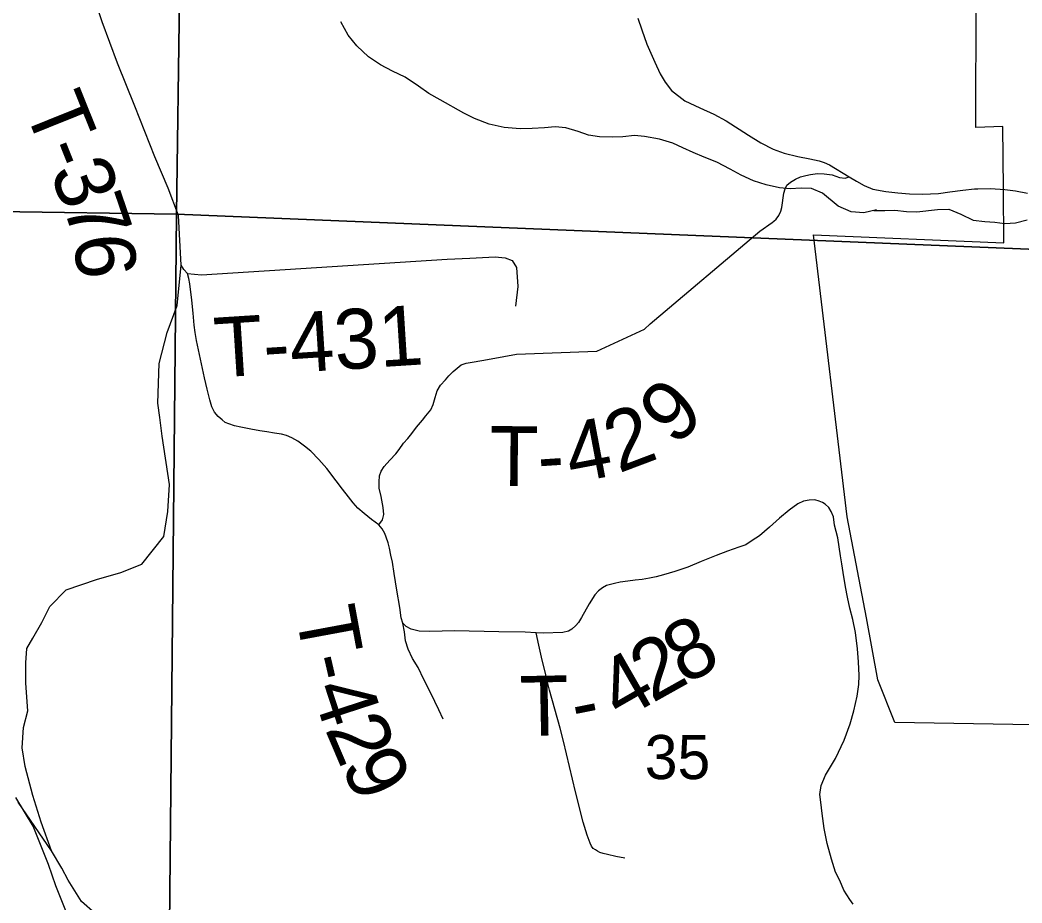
# Model space of a CAD drawing. Extents: x 2.1 to 8.9, y 14.1 to 20.9.
# Drawn here: x 6.298 to 7.249, y 17.436 to 18.274 of the extents above; entities that cross this region are included whole.
import ezdxf

# ---------------------------------------------------------------- set-up
doc = ezdxf.new("R2010")
doc.units = 0
for name, color, linetype in [('GM_X_City_Street', 7, 'Continuous'), ('GM_X_County_Road_Text', 7, 'Continuous'), ('GM_X_Interchange_Ramps', 7, 'Continuous'), ('GM_X_Minor_River_Text', 7, 'Continuous'), ('GM_X_State_Shield', 7, 'Continuous'), ('GM_X_Township_Road', 7, 'Continuous'), ('TX_P_Misc', 7, 'Continuous')]:
    doc.layers.add(name, color=color, linetype=linetype)

msp = doc.modelspace()

# ---------------------------------------------------------------- linework, layer by layer
at = {"layer": 'GM_X_City_Street'}
for p, q in [((6.3759, 18.27213), (6.36046, 18.31774)), ((6.39039, 18.23269), (6.3759, 18.27213)), ((6.40679, 18.19182), (6.39039, 18.23269)), ((6.4258, 18.14383), (6.40679, 18.19182)), ((6.43839, 18.11413), (6.4258, 18.14383)), ((7.0258, 18.11686), (7.02928, 18.11968)), ((7.02928, 18.11968), (7.03402, 18.12265)), ((7.03402, 18.12265), (7.03889, 18.12481)), ((7.03889, 18.12481), (7.04369, 18.12614)), ((7.04369, 18.12614), (7.04808, 18.12715)), ((7.04808, 18.12715), (7.05496, 18.12796)), ((7.05496, 18.12796), (7.06115, 18.12777)), ((7.06115, 18.12777), (7.06886, 18.12659)), ((7.06886, 18.12659), (7.07574, 18.12416)), ((7.07574, 18.12416), (7.08117, 18.12353)), ((7.08117, 18.12353), (7.08485, 18.12478)), ((6.44813, 18.08823), (6.43839, 18.11413)), ((7.02292, 18.10949), (7.02415, 18.11339)), ((7.02415, 18.11339), (7.0258, 18.11686)), ((7.02118, 18.09573), (7.02292, 18.10949)), ((7.01806, 18.08829), (7.02001, 18.09218)), ((7.02001, 18.09218), (7.02118, 18.09573)), ((6.45066, 18.04112), (6.44813, 18.08823)), ((7.0002, 18.07328), (7.0118, 18.08148)), ((7.0118, 18.08148), (7.01336, 18.08278)), ((7.01336, 18.08278), (7.0157, 18.08473)), ((7.0157, 18.08473), (7.01806, 18.08829)), ((6.89603, 17.98525), (7.0002, 18.07328)), ((6.46999, 18.03192), (6.70343, 18.04657)), ((6.70343, 18.04657), (6.72492, 18.04774)), ((6.72492, 18.04774), (6.74902, 18.04876)), ((6.74902, 18.04876), (6.75825, 18.04799)), ((6.75825, 18.04799), (6.76517, 18.04543)), ((6.76517, 18.04543), (6.76927, 18.03863)), ((6.44698, 18.00266), (6.45066, 18.04112)), ((6.45337, 18.03703), (6.45066, 18.04112)), ((6.45668, 18.03305), (6.45337, 18.03703)), ((6.76927, 18.03863), (6.77043, 18.02069)), ((6.45817, 18.02841), (6.45668, 18.03305)), ((6.45668, 18.03305), (6.46999, 18.03192)), ((6.45916, 18.02328), (6.45817, 18.02841)), ((6.46098, 18.00771), (6.45916, 18.02328)), ((6.77043, 18.02069), (6.76813, 18.00214)), ((6.46231, 17.99529), (6.46098, 18.00771)), ((6.43743, 17.97713), (6.44698, 18.00266)), ((6.46314, 17.98402), (6.46231, 17.99529)), ((6.43003, 17.94771), (6.43743, 17.97713)), ((6.46413, 17.97723), (6.46314, 17.98402)), ((6.46546, 17.96945), (6.46413, 17.97723)), ((6.8454, 17.95934), (6.89067, 17.98034)), ((6.89067, 17.98034), (6.89603, 17.98525)), ((6.47306, 17.93407), (6.46546, 17.96945)), ((6.76901, 17.95636), (6.8454, 17.95934)), ((6.71659, 17.94639), (6.72136, 17.94803)), ((6.72136, 17.94803), (6.72716, 17.94907)), ((6.72716, 17.94907), (6.73625, 17.95056)), ((6.73625, 17.95056), (6.74518, 17.95214)), ((6.74518, 17.95214), (6.76901, 17.95636)), ((6.42867, 17.90991), (6.43003, 17.94771)), ((6.70483, 17.93596), (6.709, 17.94013)), ((6.709, 17.94013), (6.71287, 17.94326)), ((6.71287, 17.94326), (6.71659, 17.94639)), ((6.47556, 17.92324), (6.47306, 17.93407)), ((6.69702, 17.92721), (6.70165, 17.93218)), ((6.70165, 17.93218), (6.70483, 17.93596)), ((6.47788, 17.9133), (6.47556, 17.92324)), ((6.69188, 17.91529), (6.69387, 17.92158)), ((6.69387, 17.92158), (6.69702, 17.92721)), ((6.43061, 17.89646), (6.42867, 17.90991)), ((6.47987, 17.90667), (6.47788, 17.9133)), ((6.69006, 17.90883), (6.69188, 17.91529)), ((6.48252, 17.90154), (6.47987, 17.90667)), ((6.486, 17.8974), (6.48252, 17.90154)), ((6.6831, 17.89789), (6.68791, 17.90369)), ((6.68791, 17.90369), (6.69006, 17.90883)), ((6.43276, 17.87873), (6.43061, 17.89646)), ((6.48964, 17.89408), (6.486, 17.8974)), ((6.49246, 17.89176), (6.48964, 17.89408)), ((6.4961, 17.89044), (6.49246, 17.89176)), ((6.67432, 17.88713), (6.67996, 17.89375)), ((6.67996, 17.89375), (6.6831, 17.89789)), ((6.50157, 17.88845), (6.4961, 17.89044)), ((6.50753, 17.88713), (6.50157, 17.88845)), ((6.5168, 17.88531), (6.50753, 17.88713)), ((6.52542, 17.88382), (6.5168, 17.88531)), ((6.53204, 17.88282), (6.52542, 17.88382)), ((6.5395, 17.88166), (6.53204, 17.88282)), ((6.54596, 17.8805), (6.5395, 17.88166)), ((6.66588, 17.87653), (6.66985, 17.88133)), ((6.66985, 17.88133), (6.67432, 17.88713)), ((6.43977, 17.83294), (6.43276, 17.87873)), ((6.55092, 17.87918), (6.54596, 17.8805)), ((6.55573, 17.87719), (6.55092, 17.87918)), ((6.56169, 17.87404), (6.55573, 17.87719)), ((6.56799, 17.86907), (6.56169, 17.87404)), ((6.65776, 17.86609), (6.66174, 17.87189)), ((6.66174, 17.87189), (6.66588, 17.87653)), ((6.57395, 17.86444), (6.56799, 17.86907)), ((6.58157, 17.85665), (6.57395, 17.86444)), ((6.65445, 17.86195), (6.65776, 17.86609)), ((6.58919, 17.84804), (6.58157, 17.85665)), ((6.64352, 17.85003), (6.64882, 17.85582)), ((6.64882, 17.85582), (6.65445, 17.86195)), ((6.5978, 17.83628), (6.58919, 17.84804)), ((6.63904, 17.84091), (6.64053, 17.84539)), ((6.64053, 17.84539), (6.64352, 17.85003)), ((6.60393, 17.82833), (6.5978, 17.83628)), ((6.63871, 17.83545), (6.63904, 17.84091)), ((6.63888, 17.82932), (6.63871, 17.83545)), ((6.43821, 17.80722), (6.43977, 17.83294)), ((6.60956, 17.8212), (6.60393, 17.82833)), ((6.64053, 17.82137), (6.63888, 17.82932)), ((6.6142, 17.81524), (6.60956, 17.8212)), ((6.6185, 17.81044), (6.6142, 17.81524)), ((6.64269, 17.81093), (6.64053, 17.82137)), ((7.04154, 17.81706), (7.03624, 17.81458)), ((7.04684, 17.81806), (7.04154, 17.81706)), ((7.05247, 17.81839), (7.04684, 17.81806)), ((7.05661, 17.81706), (7.05247, 17.81839)), ((7.05959, 17.81574), (7.05661, 17.81706)), ((7.06224, 17.81408), (7.05959, 17.81574)), ((6.43432, 17.78346), (6.43821, 17.80722)), ((6.62447, 17.80514), (6.6185, 17.81044)), ((6.64328, 17.80434), (6.64269, 17.81093)), ((7.02796, 17.80845), (7.01885, 17.80083)), ((7.03624, 17.81458), (7.02796, 17.80845)), ((7.06556, 17.8111), (7.06224, 17.81408)), ((7.06787, 17.80729), (7.06556, 17.8111)), ((7.07003, 17.80199), (7.06787, 17.80729)), ((6.63159, 17.79951), (6.62447, 17.80514)), ((6.63855, 17.79437), (6.63159, 17.79951)), ((6.63855, 17.79437), (6.64202, 17.79917)), ((6.64202, 17.79917), (6.64328, 17.80434)), ((7.01885, 17.80083), (7.00924, 17.79222)), ((7.07102, 17.79421), (7.07003, 17.80199)), ((6.64153, 17.79056), (6.63855, 17.79437)), ((6.64401, 17.78642), (6.64153, 17.79056)), ((6.6455, 17.78294), (6.64401, 17.78642)), ((7.00924, 17.79222), (6.9998, 17.7841)), ((7.07417, 17.78228), (7.07102, 17.79421)), ((6.41342, 17.75728), (6.43432, 17.78346)), ((6.64716, 17.77748), (6.6455, 17.78294)), ((6.64848, 17.77234), (6.64716, 17.77748)), ((6.99301, 17.77963), (6.98688, 17.77565)), ((6.9998, 17.7841), (6.99301, 17.77963)), ((7.07682, 17.76522), (7.07417, 17.78228)), ((6.64981, 17.76572), (6.64848, 17.77234)), ((6.96932, 17.76953), (6.95872, 17.76555)), ((6.98025, 17.77317), (6.96932, 17.76953)), ((6.98688, 17.77565), (6.98025, 17.77317)), ((6.6513, 17.75892), (6.64981, 17.76572)), ((6.65312, 17.74832), (6.6513, 17.75892)), ((6.94431, 17.75959), (6.93172, 17.75445)), ((6.95872, 17.76555), (6.94431, 17.75959)), ((7.07798, 17.75743), (7.07682, 17.76522)), ((6.37056, 17.74246), (6.39351, 17.74933)), ((6.39351, 17.74933), (6.41342, 17.75728)), ((6.65561, 17.73242), (6.65312, 17.74832)), ((6.91946, 17.75015), (6.9087, 17.747)), ((6.93172, 17.75445), (6.91946, 17.75015)), ((7.07914, 17.74915), (7.07798, 17.75743)), ((7.08146, 17.73574), (7.07914, 17.74915)), ((6.34159, 17.73283), (6.37056, 17.74246)), ((6.86232, 17.73888), (6.8547, 17.7369)), ((6.86762, 17.74004), (6.86232, 17.73888)), ((6.87474, 17.74104), (6.86762, 17.74004)), ((6.88187, 17.74186), (6.87474, 17.74104)), ((6.88849, 17.74269), (6.88187, 17.74186)), ((6.89545, 17.74385), (6.88849, 17.74269)), ((6.90158, 17.74501), (6.89545, 17.74385)), ((6.9087, 17.747), (6.90158, 17.74501)), ((6.32599, 17.71689), (6.34159, 17.73283)), ((6.65826, 17.71603), (6.65561, 17.73242)), ((6.84692, 17.73176), (6.8436, 17.72812)), ((6.85089, 17.73474), (6.84692, 17.73176)), ((6.8547, 17.7369), (6.85089, 17.73474)), ((7.08344, 17.7258), (7.08146, 17.73574)), ((6.8436, 17.72812), (6.83806, 17.71959)), ((7.0856, 17.71553), (7.08344, 17.7258)), ((6.31844, 17.70179), (6.32599, 17.71689)), ((6.65958, 17.70609), (6.65826, 17.71603)), ((6.83806, 17.71959), (6.831, 17.7066)), ((7.08858, 17.7046), (7.0856, 17.71553)), ((6.30991, 17.68702), (6.31844, 17.70179)), ((6.66115, 17.70101), (6.65958, 17.70609)), ((6.66455, 17.69814), (6.66115, 17.70101)), ((6.66267, 17.69286), (6.66115, 17.70101)), ((6.82803, 17.70178), (6.82538, 17.6988)), ((6.831, 17.7066), (6.82803, 17.70178)), ((7.0909, 17.69217), (7.08858, 17.7046)), ((6.66389, 17.68439), (6.66267, 17.69286)), ((6.66919, 17.69532), (6.66455, 17.69814)), ((6.67664, 17.6935), (6.66919, 17.69532)), ((6.68691, 17.69333), (6.67664, 17.6935)), ((6.71027, 17.69383), (6.68691, 17.69333)), ((6.75234, 17.69284), (6.71027, 17.69383)), ((6.77735, 17.69256), (6.75234, 17.69284)), ((6.78792, 17.69201), (6.77735, 17.69256)), ((6.79441, 17.69168), (6.78792, 17.69201)), ((6.79048, 17.68024), (6.78792, 17.69201)), ((6.81313, 17.69217), (6.79441, 17.69168)), ((6.81843, 17.6935), (6.81313, 17.69217)), ((6.82174, 17.69549), (6.81843, 17.6935)), ((6.82538, 17.6988), (6.82174, 17.69549)), ((7.09272, 17.67677), (7.0909, 17.69217)), ((6.30433, 17.67717), (6.30991, 17.68702)), ((6.66621, 17.6766), (6.66389, 17.68439)), ((6.30334, 17.66339), (6.30433, 17.67717)), ((6.67035, 17.66749), (6.66621, 17.6766)), ((6.79353, 17.66593), (6.79048, 17.68024)), ((7.09371, 17.66451), (7.09272, 17.67677)), ((6.30334, 17.64435), (6.30334, 17.66339)), ((6.67565, 17.65905), (6.67035, 17.66749)), ((6.79588, 17.65634), (6.79353, 17.66593)), ((7.09454, 17.65159), (7.09371, 17.66451)), ((6.68128, 17.64778), (6.67565, 17.65905)), ((6.79855, 17.64531), (6.79588, 17.65634)), ((6.30531, 17.6181), (6.30334, 17.64435)), ((6.68774, 17.63486), (6.68128, 17.64778)), ((6.8006, 17.63747), (6.79855, 17.64531)), ((7.09404, 17.64281), (7.09454, 17.65159)), ((6.69552, 17.6188), (6.68774, 17.63486)), ((6.81072, 17.60163), (6.8006, 17.63747)), ((7.09255, 17.63188), (7.09404, 17.64281)), ((7.08924, 17.6178), (7.09255, 17.63188)), ((6.30104, 17.60202), (6.30531, 17.6181)), ((6.69958, 17.60992), (6.69552, 17.6188)), ((7.08576, 17.60555), (7.08924, 17.6178)), ((7.0803, 17.59014), (7.08576, 17.60555)), ((6.29973, 17.58298), (6.30104, 17.60202)), ((6.81384, 17.58923), (6.81072, 17.60163)), ((6.82503, 17.54121), (6.81384, 17.58923)), ((7.07202, 17.57275), (7.0803, 17.59014)), ((6.30268, 17.56526), (6.29973, 17.58298)), ((7.06257, 17.55685), (7.07202, 17.57275)), ((6.30991, 17.53769), (6.30268, 17.56526)), ((7.05843, 17.54708), (7.06257, 17.55685)), ((6.83233, 17.51237), (6.82503, 17.54121)), ((7.05694, 17.53863), (7.05843, 17.54708)), ((6.32763, 17.48517), (6.29596, 17.53112)), ((6.31778, 17.51241), (6.30991, 17.53769)), ((7.05794, 17.53118), (7.05694, 17.53863)), ((7.05926, 17.52041), (7.05794, 17.53118)), ((7.06108, 17.50616), (7.05926, 17.52041)), ((6.32763, 17.48517), (6.31778, 17.51241)), ((6.83621, 17.49997), (6.83233, 17.51237)), ((7.06407, 17.49209), (7.06108, 17.50616)), ((6.83911, 17.49228), (6.83621, 17.49997)), ((6.84032, 17.48955), (6.83911, 17.49228)), ((7.06804, 17.47718), (7.06407, 17.49209)), ((6.33747, 17.4686), (6.32763, 17.48517)), ((6.84207, 17.48734), (6.84032, 17.48955)), ((6.84405, 17.48589), (6.84207, 17.48734)), ((6.84588, 17.4846), (6.84405, 17.48589)), ((6.84816, 17.48361), (6.84588, 17.4846)), ((6.85151, 17.48262), (6.84816, 17.48361)), ((6.85547, 17.48156), (6.85151, 17.48262)), ((6.86338, 17.47973), (6.85547, 17.48156)), ((6.8719, 17.47821), (6.86338, 17.47973)), ((7.07202, 17.46476), (7.06804, 17.47718)), ((6.34338, 17.45724), (6.33747, 17.4686)), ((7.07599, 17.45681), (7.07202, 17.46476)), ((6.35631, 17.43691), (6.34338, 17.45724)), ((7.07997, 17.4477), (7.07599, 17.45681)), ((7.08543, 17.43875), (7.07997, 17.4477)), ((6.36907, 17.42545), (6.35631, 17.43691)), ((7.08874, 17.43428), (7.08543, 17.43875))]:
    msp.add_line(p, q, dxfattribs=at)
at = {"layer": 'GM_X_Interchange_Ramps'}
for p, q in [((6.45993, 19.12233), (6.44653, 18.08952)), ((6.44653, 18.08952), (6.45993, 19.12233)), ((6.44653, 18.08952), (5.51984, 18.10239)), ((5.51984, 18.10239), (6.44653, 18.08952)), ((6.44653, 18.08952), (6.43657, 17.11137)), ((6.43657, 17.11137), (6.44653, 18.08952)), ((7.45701, 18.04776), (6.44653, 18.08952)), ((6.44653, 18.08952), (7.45701, 18.04776))]:
    msp.add_line(p, q, dxfattribs=at)
at = {"layer": 'GM_X_State_Shield'}
for p, q in [((6.88446, 18.27551), (6.88802, 18.26449)), ((6.88802, 18.26449), (6.89288, 18.25065)), ((6.89288, 18.25065), (6.90032, 18.23369)), ((6.90032, 18.23369), (6.9056, 18.22257)), ((6.9056, 18.22257), (6.91012, 18.21472)), ((6.91012, 18.21472), (6.91624, 18.20666)), ((6.91624, 18.20666), (6.92895, 18.19693)), ((6.92895, 18.19693), (6.94306, 18.19026)), ((6.94306, 18.19026), (6.95655, 18.18449)), ((6.95655, 18.18449), (6.96815, 18.17795)), ((6.96815, 18.17795), (6.98949, 18.16433)), ((6.98949, 18.16433), (7.0011, 18.15724)), ((7.0011, 18.15724), (7.01271, 18.15106)), ((7.01271, 18.15106), (7.0232, 18.14723)), ((7.0232, 18.14723), (7.03606, 18.14404)), ((7.03606, 18.14404), (7.04749, 18.14202)), ((7.04749, 18.14202), (7.0566, 18.14004)), ((7.0566, 18.14004), (7.06125, 18.13855)), ((7.06125, 18.13855), (7.06636, 18.13632)), ((7.06636, 18.13632), (7.08485, 18.12478)), ((7.08485, 18.12478), (7.09176, 18.12064)), ((7.09176, 18.12064), (7.09924, 18.11672)), ((7.09924, 18.11672), (7.10729, 18.11316)), ((7.10729, 18.11316), (7.11971, 18.11085)), ((7.11971, 18.11085), (7.13108, 18.10976)), ((7.13108, 18.10976), (7.14226, 18.10887)), ((7.16964, 18.10915), (7.18048, 18.11056)), ((7.18048, 18.11056), (7.19272, 18.11234)), ((7.19272, 18.11234), (7.20384, 18.11352)), ((7.20384, 18.11352), (7.20709, 18.11359)), ((7.20709, 18.11359), (7.21899, 18.11384)), ((7.21899, 18.11384), (7.23279, 18.11293)), ((7.23279, 18.11293), (7.24297, 18.11147)), ((7.24297, 18.11147), (7.25412, 18.10949)), ((7.14226, 18.10887), (7.15446, 18.10838)), ((7.15446, 18.10838), (7.16964, 18.10915))]:
    msp.add_line(p, q, dxfattribs=at)
at = {"layer": 'GM_X_Township_Road'}
for p, q in [((7.20512, 18.17173), (7.20609, 18.4212)), ((7.23087, 18.17248), (7.20512, 18.17173)), ((7.23143, 18.11348), (7.23087, 18.17248)), ((7.23174, 18.06206), (7.23143, 18.11348)), ((7.08319, 17.80195), (7.05118, 18.06988)), ((7.05118, 18.06988), (7.23174, 18.06206)), ((7.10144, 17.70634), (7.08319, 17.80195)), ((7.11206, 17.64736), (7.10144, 17.70634)), ((7.12815, 17.60681), (7.11206, 17.64736)), ((7.25901, 17.60459), (7.12815, 17.60681))]:
    msp.add_line(p, q, dxfattribs=at)
at = {"layer": 'TX_P_Misc'}
for p, q in [((6.60937, 18.25935), (6.60251, 18.27207)), ((6.61766, 18.24934), (6.60937, 18.25935)), ((6.62864, 18.23865), (6.61766, 18.24934)), ((6.6399, 18.23101), (6.62864, 18.23865)), ((6.65148, 18.22528), (6.6399, 18.23101)), ((6.66345, 18.21957), (6.65148, 18.22528)), ((6.67626, 18.21085), (6.66345, 18.21957)), ((6.68598, 18.20392), (6.67626, 18.21085)), ((6.69682, 18.19779), (6.68598, 18.20392)), ((6.71926, 18.18518), (6.69682, 18.19779)), ((6.7293, 18.18017), (6.71926, 18.18518)), ((6.74315, 18.17489), (6.7293, 18.18017)), ((6.75733, 18.17153), (6.74315, 18.17489)), ((6.77256, 18.17049), (6.75733, 18.17153)), ((6.78396, 18.17085), (6.77256, 18.17049)), ((6.79573, 18.17122), (6.78396, 18.17085)), ((6.80597, 18.1723), (6.79573, 18.17122)), ((6.81588, 18.17147), (6.80597, 18.1723)), ((6.82777, 18.16804), (6.81588, 18.17147)), ((6.83738, 18.16453), (6.82777, 18.16804)), ((6.84808, 18.16297), (6.83738, 18.16453)), ((6.86063, 18.1626), (6.84808, 18.16297)), ((6.87013, 18.1629), (6.86063, 18.1626)), ((6.88112, 18.164), (6.87013, 18.1629)), ((6.89065, 18.16316), (6.88112, 18.164)), ((6.9048, 18.16056), (6.89065, 18.16316)), ((6.91746, 18.15677), (6.9048, 18.16056)), ((6.9271, 18.15251), (6.91746, 18.15677)), ((6.93675, 18.14787), (6.9271, 18.15251)), ((6.94715, 18.14363), (6.93675, 18.14787)), ((6.95947, 18.13868), (6.94715, 18.14363)), ((6.97183, 18.13222), (6.95947, 18.13868)), ((6.98227, 18.12646), (6.97183, 18.13222)), ((6.99422, 18.12113), (6.98227, 18.12646)), ((7.00613, 18.11732), (6.99422, 18.12113)), ((7.01877, 18.11429), (7.00613, 18.11732)), ((7.02906, 18.11347), (7.01877, 18.11429)), ((7.0393, 18.11417), (7.02906, 18.11347)), ((7.0492, 18.11372), (7.0393, 18.11417)), ((7.0596, 18.10948), (7.0492, 18.11372)), ((7.07443, 18.097), (7.0596, 18.10948)), ((7.08676, 18.09168), (7.07443, 18.097)), ((7.09896, 18.09054), (7.08676, 18.09168)), ((7.11089, 18.09356), (7.09896, 18.09054)), ((7.10832, 18.09291), (7.11879, 18.09281)), ((7.11879, 18.09281), (7.12829, 18.09307)), ((7.12829, 18.09307), (7.13934, 18.09185)), ((7.13934, 18.09185), (7.14923, 18.09173)), ((7.14923, 18.09173), (7.16893, 18.09379)), ((7.16893, 18.09379), (7.17956, 18.09408)), ((7.17956, 18.09408), (7.19109, 18.08944)), ((7.19109, 18.08944), (7.20265, 18.08366)), ((7.20265, 18.08366), (7.2137, 18.08244)), ((7.2137, 18.08244), (7.22321, 18.08193)), ((7.22321, 18.08193), (7.23275, 18.08067)), ((7.23275, 18.08067), (7.24299, 18.08133)), ((7.24299, 18.08133), (7.25394, 18.08391)), ((6.31021, 17.50852), (6.29387, 17.53567)), ((6.32481, 17.47221), (6.31021, 17.50852)), ((6.33196, 17.45177), (6.32481, 17.47221)), ((6.345, 17.41848), (6.33196, 17.45177))]:
    msp.add_line(p, q, dxfattribs=at)

# ---------------------------------------------------------------- texts
at = {"layer": 'GM_X_County_Road_Text'}
msp.add_text('35', height=0.041856, rotation=0.00001, dxfattribs=at).set_placement((6.89088, 17.55315))
at = {"layer": 'GM_X_Minor_River_Text'}
for s, height, rotation, p in [('T', 0.05682, 291.92397, (6.30111, 18.19072)), ('-', 0.05682, 291.77677, (6.31697, 18.15133)), ('3', 0.05682, 291.18584, (6.32557, 18.1298)), ('7', 0.05682, 288.92043, (6.33801, 18.09773)), ('6', 0.05682, 275.84885, (6.34863, 18.06796)), ('T-431', 0.056818, 3.64643, (6.48382, 17.93425)), ('9', 0.05682, 42.74308, (6.91898, 17.86799)), ('2', 0.05682, 20.68486, (6.86607, 17.84316)), ('4', 0.05682, 10.67627, (6.82128, 17.83376)), ('T', 0.05682, 359.43859, (6.74341, 17.83156)), ('-', 0.05682, 3.7909, (6.79061, 17.83128)), ('T', 0.05682, 280.51133, (6.5592, 17.71153)), ('8', 0.05682, 28.50413, (6.92848, 17.64198)), ('2', 0.05682, 29.19815, (6.89808, 17.62499)), ('4', 0.05682, 29.85682, (6.86788, 17.60765)), ('-', 0.05682, 283.02657, (6.5675, 17.66708)), ('T', 0.05682, 1.07575, (6.77283, 17.59405)), ('4', 0.05682, 288.05704, (6.57422, 17.63911)), ('-', 0.05682, 11.33885, (6.82634, 17.59605)), ('2', 0.05682, 293.0875, (6.58698, 17.60074)), ('9', 0.05682, 295.60274, (6.60183, 17.56607))]:
    msp.add_text(s, height=height, rotation=rotation, dxfattribs=at).set_placement(p)

doc.saveas('drawing.dxf')
